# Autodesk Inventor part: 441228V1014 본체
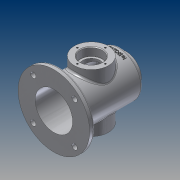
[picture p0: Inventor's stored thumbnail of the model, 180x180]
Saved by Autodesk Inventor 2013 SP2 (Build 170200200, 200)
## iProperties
Created: 2014-12
Part Number: 441228V1014 본체
Material: 알루미늄 6061
Document SubType Name: Modeling
Designer: CADB105
Density: 2.71 g/cm^3
Mass: 478.804 g
Surface Area: 623.216 cm^2
Volume: 176.681 cm^3
Author: CADB105
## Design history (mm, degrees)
sketch "스케치1"
  geometry: L1 (0, 86.22)-(0, -86.22); L2 (-52.5, -47)-(0, -47); L3 (52.5, -47)-(52.5, -55); L4 (0, -55)-(-52.5, -55); L5 (-52.5, -55)-(-52.5, -47); L6 (-32.5, 43)-(0, 43); L7 (0, -55)-(-32.5, -55); L8 (-32.5, -55)-(-32.5, 43); L9 (-32.5, -55)-(0, -55); L10 (0, 43)-(0, -55); L11 (0, -55)-(0, -47); 2 further points
  constraints: 22 end point, 3 collinear, 3 parallel, 2 horizontal, 2 point on line, 2 vertical alignment, 1 coincident, 1 midpoint, 1 perpendicular, 1 vertical
  dimensions: "d0" = 55 distance from line of point (0, 0) L4; "d1" = 8 distance between parallel lines of L2 L4; "d4" = 65 diameter of L8 L1; "d5" = 98 distance of L7.end L6.start; "d8" = 105 diameter of L5 L1
revolve "회전1" stored, may be unused: angle "d6" = 90 deg
feature "쉘1" dims "d7" = 5
revolve "회전2" stored, may be unused: angle "d9" = 90 deg
sketch "스케치2"
  geometry: C1 r 52.5 at (0, 0) reference
sketch "스케치3"
  geometry: C1 r 27.5 at (0, 0) reference
extrude "돌출1" cut sketch "스케치3" distance "d10" = 15; taper "d11" = 0 deg
sketch "스케치4"
  geometry: C1 r 32.5 at (0, 0) reference; C2 r 22.5 at (0, 0)
  constraints: 1 centre point, 1 coincident
  dimensions: "d12" = 45 diameter of C2
extrude "돌출2" join sketch "스케치4" distance "d13" = 8; taper "d14" = 0 deg
node "작업 평면1"
sketch "스케치5"
  geometry: C1 r 25 at (0, 0); 1 further point
  constraints: 1 centre point, 1 coincident
  dimensions: "d16" = 50 diameter of C1
extrude "돌출3" join sketch "스케치5" stored distance "d17" = 8; taper "d18" = 0 deg
hole "구멍1" diameter "d21" = 25; stored, may be unused: countersink angle "d25" = 90 deg, drill point angle "d27" = 0 deg; dims "d19" = 10, "d20" = 10, "d22" = 6, "d23" = 32, "d24" = 12, "d26" = 8
chamfer "모따기1" distance "d28" = 1; stored, may be unused: second distance "d29" = 2, angle "d30" = 45 deg
fillet "모깎기1" dims "d31" = 0.3
sketch "스케치6"
  geometry: C1 r 25 at (0, 0) reference; 1 further point
  constraints: 1 vertical alignment
  dimensions: "d32" = 20.5 distance of point (0, 20.5) C1.centre
hole "구멍2" sketch "스케치6" at (0, 20.5) diameter "d33" = 2.459; stored, may be unused: countersink angle "d37" = 90 deg, drill point angle "d39" = 118 deg; dims "d34" = 6, "d35" = 32, "d36" = 12, "d38" = 8
sketch "스케치7"
  geometry: C1 r 22.5 at (0, 0) reference; 1 further point
  constraints: 1 vertical alignment
  dimensions: "d43" = 17.5 distance of point (0, 17.5) C1.centre
hole "구멍3" sketch "스케치7" at (0, 17.5) diameter "d44" = 2.459; stored, may be unused: countersink angle "d48" = 90 deg, drill point angle "d50" = 118 deg; dims "d45" = 6, "d46" = 4, "d47" = 2, "d49" = 8
hole "구멍4" diameter "d56" = 27; stored, may be unused: countersink angle "d60" = 90 deg, drill point angle "d62" = 0 deg; dims "d54" = 10, "d55" = 10, "d57" = 6, "d58" = 4, "d59" = 2, "d61" = 8
sketch "스케치8" dims "d63" = 86
  geometry: L1 (-52.5, 0)-(52.5, 0); L2 (0, 0)-(-30.406, 30.406); C1 r 32.5 at (0, 0) reference; A1 r 52.5 centre (0, 0) between (-52.5, 0) and (52.5, 0) reference; 2 further points
  constraints: 4 end point, 3 coincident, 2 point on circle, 1 horizontal, 1 midpoint, 3 other
  dimensions: "d64" = 45 deg angle of L1 L2
hole "구멍5" sketch "스케치8" at (-30.406, 30.406) diameter "d66" = 8; stored, may be unused: countersink angle "d70" = 90 deg, drill point angle "d72" = 0 deg; dims "d67" = 6, "d68" = 4, "d69" = 2, "d71" = 8
node "작업 평면3"
sketch "스케치9"
  geometry: L1 (32.5, 43)-(-32.5, 43) reference; 2 further points
  constraints: 1 vertical alignment, 1 other
  dimensions: "d77" = 9 distance from line of L1 point (0, 34)
feature "엠보싱1" sketch "스케치9" dims "d78" = 1, "d79" = 0
fillet "모깎기2" dims "d80" = 3
chamfer "모따기2" distance "d81" = 1; stored, may be unused: second distance "d82" = 2, angle "d83" = 45 deg
fillet "모깎기3" dims "d84" = 3
node "솔리드1"
pattern_circular "원형 패턴1" dims angle "d41" = 360 deg
mirror "대칭1"
pattern_circular "원형 패턴2" dims angle "d52" = 360 deg
pattern_circular "원형 패턴3" dims angle "d74" = 360 deg
other parameters: "d15" = 42.5, "d76" = 32.5
